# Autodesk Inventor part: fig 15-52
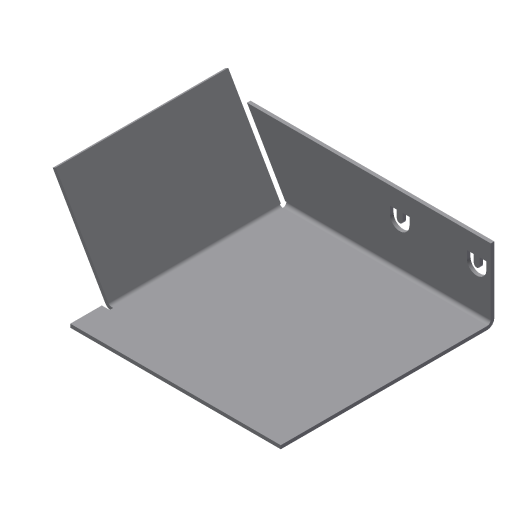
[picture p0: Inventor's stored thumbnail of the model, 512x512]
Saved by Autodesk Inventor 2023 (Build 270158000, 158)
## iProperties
Created: 2002-04
Part Number: fig 15-52
Document SubType Name: Sheet Metal
Density: 1 g/cm^3
Sheet Metal Rule: Default
Material: Generic
Appearance: Default
Control State: 0
Master: False
Checked Out: False
Shininess: 77.0
Angle Display Precision: 2
Document Length Units: 11269
Document Angle Units: 11279
Document Time Units: 11290
Document Mass Units: 11283
Document Length Units Precision: 3
Document Angle Units Precision: 2
Density: 0.0
Volumn: 0.0
Area: 0.0
PropertySet Name: Model Information
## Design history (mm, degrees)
node "Face1"
  sketch "Sketch1"
    geometry: L1 (12.647, 25.882)-(12.647, -14.118); L2 (12.647, -14.118)-(-17.353, -14.118); L3 (-17.353, -14.118)-(-17.353, 15.882); L4 (-17.353, 15.882)-(-2.353, 15.882); L5 (-2.353, 15.882)-(-2.353, 25.882); L6 (-2.353, 25.882)-(12.647, 25.882); 1 further point
    constraints: 12 end point, 4 parallel, 1 perpendicular
    dimensions: "d5" = 30 distance of L2.end L3.end; "d6" = 10 distance of L4.end L5.end; "d7" = 15 distance of L3.end L4.end; "d25" = 15 distance of L5.end L1.start
sketch "Sketch3"
  geometry: L1 (10, -15)-(10, 0)
  constraints: 2 end point
feature "Fold3" sketch "Sketch3" dims "d26" = 0.5 (= BendRadius), "d27" = 90 deg, "d28" = 0.5 (= BendRadius), "d96" = 0.5 (= BendReliefWidth), "d97" = 0.25 (= BendReliefDepth), "d98" = 1 (= MinimumRemnant), "d112" = 0.5 (= Thickness), "SeamGap" = 0.01
node "Flange2"
sketch "Sketch6"
  geometry: L1 (-6.914, 3.413)-(-5.843, 3.413); L2 (-5.843, 0.624)-(-6.914, 0.624); L3 (-6.914, 2.432)-(-5.843, 2.432); L4 (-5.843, 1.605)-(-6.914, 1.605); L5 (-6.914, 0.624)-(-6.914, 1.605); L6 (-6.914, 2.432)-(-6.914, 3.413); L7 (-6.914, 12.568)-(-6.914, 11.587); L8 (-6.914, 14.376)-(-6.914, 13.395); L9 (-6.914, 11.587)-(-5.843, 11.587); L10 (-5.843, 14.376)-(-6.914, 14.376); L11 (-6.914, 12.568)-(-5.843, 12.568); L12 (-5.843, 13.395)-(-6.914, 13.395); A1 r 1.394 centre (-5.843, 2.018) between (-5.843, 0.624) and (-5.843, 3.413); A2 r 0.413 centre (-5.843, 2.018) between (-5.843, 1.605) and (-5.843, 2.432); A3 r 1.394 centre (-5.843, 12.982) between (-5.843, 11.587) and (-5.843, 14.376); A4 r 0.413 centre (-5.843, 12.982) between (-5.843, 12.568) and (-5.843, 13.395)
  constraints: 24 end point, 8 point on circle, 4 centre point, 3 equal length, 1 perpendicular
cut "Cut1" sketch "Sketch6" dims "d49" = 0.5 (= Thickness), "d50" = 0
feature "Corner3" dims "d107" = 2 (= CornerReliefSize), "d108" = 0.5 (= BendRadius), "d109" = 0.5 (= GapSize), "d110" = 0, "d111" = 10, "d112" = 0.5 (= Thickness)
body "Solid1"
face "Plate1" dims "d112" = 0.5 (= Thickness)
sketch "Sketch5"
  geometry: L1 (20, 0)-(5, 0); L2 (5, 0)-(5, 15); L3 (5, 15)-(20, 15); L4 (20, 15)-(20, 0)
  constraints: 8 end point
face "Plate6" dims "d35" = 10, "d36" = 5, "d38" = 15, "d39" = 60 deg, "d40" = 0.5 (= BendRadius), "d112" = 0.5 (= Thickness), "MinimumRemnant" = 1 (= 2 x Thickness), "BendReliefWidth" = 0.5 (= Thickness)
bend "Bend5" dims "d38" = 15, "d39" = 60 deg, "d40" = 0.5 (= BendRadius), "d99" = 0.5 (= BendReliefWidth), "d100" = 0.25 (= BendReliefDepth), "d101" = 1 (= MinimumRemnant), "d112" = 0.5 (= Thickness), "SeamGap" = 0.01, "MinimumRemnant" = 1 (= 2 x Thickness), "BendReliefWidth" = 0.5 (= Thickness), "TransitionRadius" = 0.5 (= BendRadius)
other parameters: "Thickness" = 0.5, "BendRadius" = 0.5 (= Thickness), "BendReliefDepth" = 0.25 (= 0.5 x Thickness), "CornerReliefSize" = 2 (= 4 x Thickness), "d0" = 0.5 (= BendRadius), "d13" = 0.5 (= BendRadius), "d31" = 0.5 (= BendRadius), "d37" = 0.5 (= BendRadius), "JacobiRadiusSize" = 0.5 (= Thickness), "GapSize" = 0.5 (= Thickness)
